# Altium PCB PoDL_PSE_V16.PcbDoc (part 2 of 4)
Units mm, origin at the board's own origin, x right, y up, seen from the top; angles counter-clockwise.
Board outline 155 x 86.5 mm, 4 copper layers (Top Layer, Signal Layer 2, Signal Layer 3, Bottom Layer), stack 1.586 mm thick; 431 components, 281 nets, 1286 pads, 864 vias.
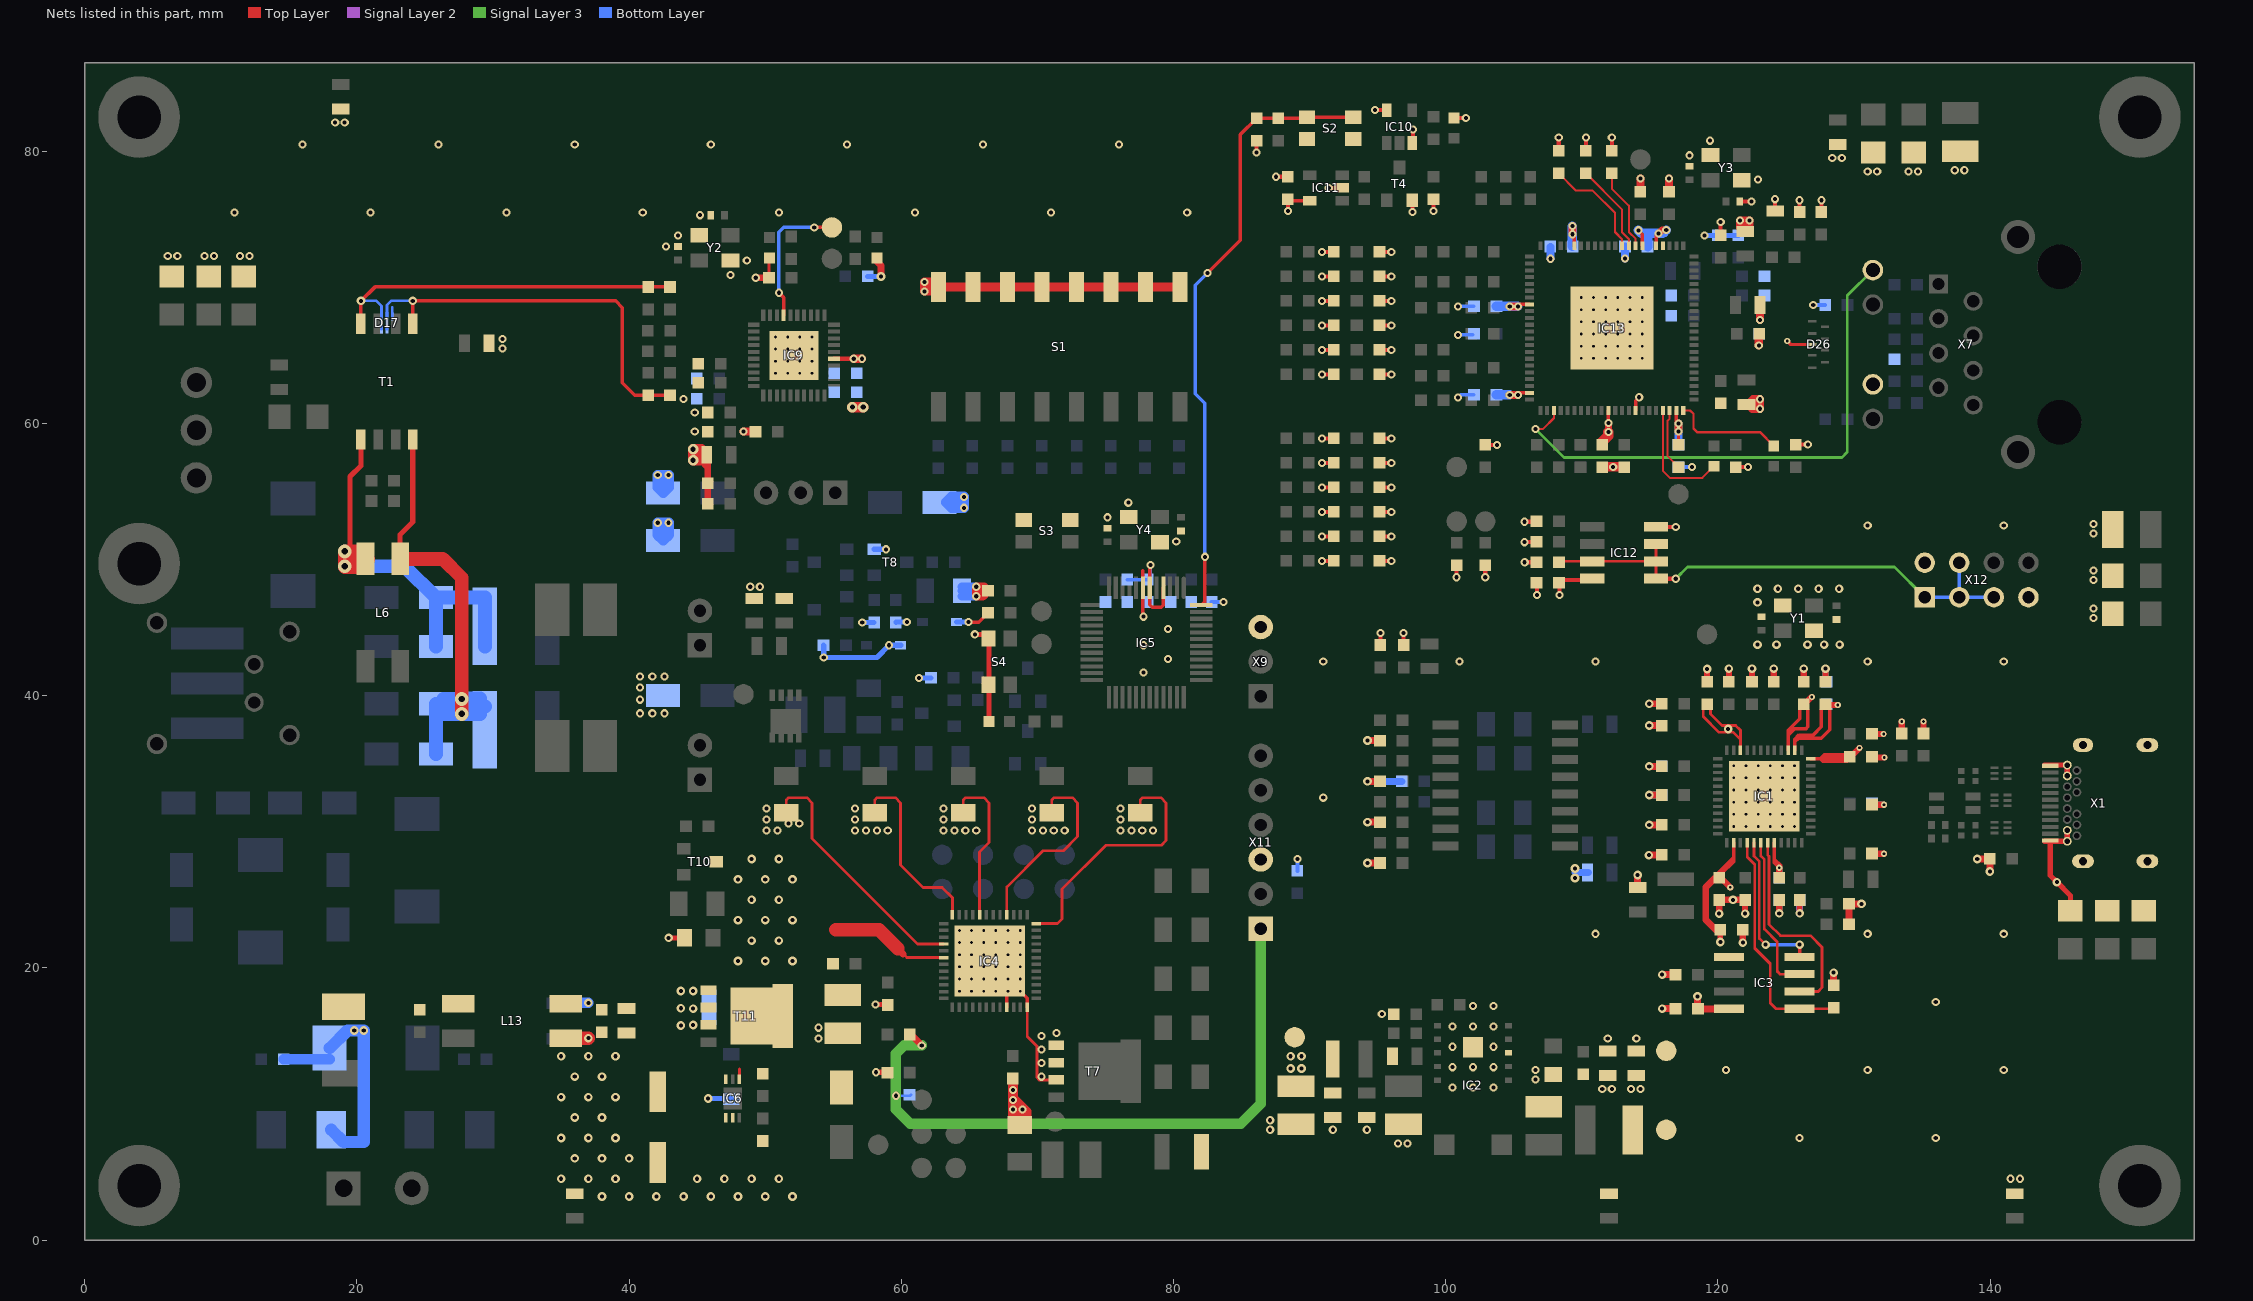
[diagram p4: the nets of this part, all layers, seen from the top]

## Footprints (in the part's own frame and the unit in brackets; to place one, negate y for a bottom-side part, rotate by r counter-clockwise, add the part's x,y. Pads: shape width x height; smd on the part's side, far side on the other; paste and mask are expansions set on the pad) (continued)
"QFN-88 12X12MM" [mm]
  rect 0.65x0.3 smd: 1(-6.05,5.25) 2(-6.05,4.75) 3(-6.05,4.25) 4(-6.05,3.75) 5(-6.05,3.25) 6(-6.05,2.75) 7(-6.05,2.25) 8(-6.05,1.75) 9(-6.05,1.25) 10(-6.05,0.75) 11(-6.05,0.25) 12(-6.05,-0.25) 13(-6.05,-0.75) 14(-6.05,-1.25) 15(-6.05,-1.75) 16(-6.05,-2.25) 17(-6.05,-2.75) 18(-6.05,-3.25) 19(-6.05,-3.75) 20(-6.05,-4.25) 21(-6.05,-4.75) 22(-6.05,-5.25) 45(6.05,-5.25) 46(6.05,-4.75) 47(6.05,-4.25) 48(6.05,-3.75) 49(6.05,-3.25) 50(6.05,-2.75) 51(6.05,-2.25) 52(6.05,-1.75) 53(6.05,-1.25) 54(6.05,-0.75) 55(6.05,-0.25) 56(6.05,0.25) 57(6.05,0.75) 58(6.05,1.25) 59(6.05,1.75) 60(6.05,2.25) 61(6.05,2.75) 62(6.05,3.25) 63(6.05,3.75) 64(6.05,4.25) 65(6.05,4.75) 66(6.05,5.25)
  rect 0.3x0.65 smd: 23(-5.25,-6.05) 24(-4.75,-6.05) 25(-4.25,-6.05) 26(-3.75,-6.05) 27(-3.25,-6.05) 28(-2.75,-6.05) 29(-2.25,-6.05) 30(-1.75,-6.05) 31(-1.25,-6.05) 32(-0.75,-6.05) 33(-0.25,-6.05) 34(0.25,-6.05) 35(0.75,-6.05) 36(1.25,-6.05) 37(1.75,-6.05) 38(2.25,-6.05) 39(2.75,-6.05) 40(3.25,-6.05) 41(3.75,-6.05) 42(4.25,-6.05) 43(4.75,-6.05) 44(5.25,-6.05) 67(5.25,6.05) 68(4.75,6.05) 69(4.25,6.05) 70(3.75,6.05) 71(3.25,6.05) 72(2.75,6.05) 73(2.25,6.05) 74(1.75,6.05) 75(1.25,6.05) 76(0.75,6.05) 77(0.25,6.05) 78(-0.25,6.05) 79(-0.75,6.05) 80(-1.25,6.05) 81(-1.75,6.05) 82(-2.25,6.05) 83(-2.75,6.05) 84(-3.25,6.05) 85(-3.75,6.05) 86(-4.25,6.05) 87(-4.75,6.05) 88(-5.25,6.05)
  rect 6.1x6.1 smd: 89(0,0)
  silkscreen extent -6.5,5.88 -6.25,6.13, body extent -6.05,-6.05 6.05,6.05, height 1
"QFP-48 7x7MM" [mm] "TQFP, 48-Leads, Body 9.2x9.2mm (max), Pitch 0.50mm, IPC Medium Density"
  oval 1.65x0.3 smd: 1(-4.025,2.75)
  rect 1.65x0.3 smd: 2(-4.025,2.25) 3(-4.025,1.75) 4(-4.025,1.25) 5(-4.025,0.75) 6(-4.025,0.25) 7(-4.025,-0.25) 8(-4.025,-0.75) 9(-4.025,-1.25) 10(-4.025,-1.75) 11(-4.025,-2.25) 12(-4.025,-2.75) 25(4.025,-2.75) 26(4.025,-2.25) 27(4.025,-1.75) 28(4.025,-1.25) 29(4.025,-0.75) 30(4.025,-0.25) 31(4.025,0.25) 32(4.025,0.75) 33(4.025,1.25) 34(4.025,1.75) 35(4.025,2.25) 36(4.025,2.75)
  rect 0.3x1.65 smd: 13(-2.75,-4.025) 14(-2.25,-4.025) 15(-1.75,-4.025) 16(-1.25,-4.025) 17(-0.75,-4.025) 18(-0.25,-4.025) 19(0.25,-4.025) 20(0.75,-4.025) 21(1.25,-4.025) 22(1.75,-4.025) 23(2.25,-4.025) 24(2.75,-4.025) 37(2.75,4.025) 38(2.25,4.025) 39(1.75,4.025) 40(1.25,4.025) 41(0.75,4.025) 42(0.25,4.025) 43(-0.25,4.025) 44(-0.75,4.025) 45(-1.25,4.025) 46(-1.75,4.025) 47(-2.25,4.025) 48(-2.75,4.025)
  silkscreen extent -4.2,-2.8 2.8,3.58, body extent -4.5,-4.5 4.5,4.5, height 1.45
RJ45_74990112116A [mm] "Ethernet Connectors WR-MJ Feml Shld Hztl 8P8C Tab Up LED&EMI"
  round 2.5 hole 1.6: B1(-7.9,3.05) B2(7.9,3.05)
  round 3.2 hole 3.25 unplated: H1(-5.715,0)
  round 3.25 hole 3.25 unplated: H2(5.715,0)
  rect 1.4x1.4 hole 0.9: P1(4.445,8.89)
  round 1.4 hole 0.9: P2(3.175,6.35) P3(1.905,8.89) P4(0.635,6.35) P5(-0.635,8.89) P6(-1.905,6.35) P7(-3.175,8.89) P8(-4.445,6.35)
  round 1.52 hole 1.02: P9(5.465,13.72) P10(2.925,13.72) P11(-2.925,13.72) P12(-5.465,13.72)
  silkscreen extent -9.99,-10.8 9.99,14.5, body extent -10.27,-10.8 10.27,14.5, height 15.78
SET [mm]
  rect 1.96x3.15 smd: 1(-2.45,0) 2(2.45,0)
  body extent -3.05,-1.4 3.05,1.29, height 2.68
SMA/DO-214AC [mm]
  rect 2.5x1.7 smd: 1(-2,0) 2(2,0)
  silkscreen extent -2.8,-1.5 2.8,1.5, body extent -2.65,-1.3 2.55,1.3, height 2.4
SMB/DO-214AA [mm]
  rect 2.159x2.743 smd: 1(-2.21,0) 2(2.21,0)
  silkscreen extent -2.16,-1.91 2.16,1.91, body extent -2.7,-1.74 2.7,1.86, height 2.3
SMC/DO-214AB [mm]
  rect 2.5x3.3 smd: 1(-3.4,0) 2(3.4,0)
  silkscreen extent -4.1,-3.15 4.1,3.15, body extent -3.97,-2.95 3.97,2.95, height 2.3
"SMT 6.3mmx5.5mm - WE" [mm]
  rect 1.2x3 smd: 1(0,2.6) 2(0,-2.6)
  silkscreen extent -3.4,-3.4 3.4,3.4, body extent -3.3,-3.65 3.3,3.65, height 5.5
SO-8 [mm]
  rect 0.72x1.78 smd: 1(-1.905,-2.34) 2(-0.635,-2.34) 3(0.635,-2.34) 4(1.905,-2.34) 5(1.905,2.34) 6(0.635,2.34) 7(-0.635,2.34) 8(-1.905,2.34)
  silkscreen extent -2.73,-2.22 2.5,1.4, body extent -2.5,-3.17 2.5,3.17, height 1.88
SO-8N [mm]
  rect 0.6x2.2 smd: 1(-1.905,-2.6) 2(-0.635,-2.6) 3(0.635,-2.6) 4(1.905,-2.6) 5(1.905,2.6) 6(0.635,2.6) 7(-0.635,2.6) 8(-1.905,2.6)
  silkscreen extent -2.87,-2.46 2.5,1.1, body extent -2.5,-3.17 2.5,3.17, height 1.88
SOD-123 [mm] "On Semi recommended land pattern"
  rect 0.915x1.22 smd: 1(-1.637,0) 2(1.637,0)
  silkscreen extent -2.74,-1.17 2.03,1.17, body extent -1.93,-0.9 1.93,0.9, height 1.35
SOD-323 [mm]
  rect 0.8x0.6 smd: 1(-1.25,0) 2(1.25,0)
  silkscreen extent -0.8,-0.7 0.8,0.7, body extent -1.3,-0.67 1.3,0.68, height 1.1
SOT-23 [mm]
  rect 0.85x1 smd: 1(-0.95,-1.2) 2(0.95,-1.2) 3(0,1.2)
  silkscreen extent -1.43,-0.3 1.43,1.2, body extent -1.46,-1.17 1.46,1.17, height 1
SOT-23-5 [mm] "TSOP-5, Case483-2"
  rect 0.7x1 smd: 1(-0.95,-1.2) 2(0,-1.2) 3(0.95,-1.2) 4(0.95,1.2) 5(-0.95,1.2)
  silkscreen extent -1.77,-1.57 1.53,0.88, body extent -1.46,-1.17 1.46,1.17, height 1
"TESTPOINT 1.5mm"#1 [mm]
  round 1.5 smd paste-1.5: 1(0,0)
"TESTPOINT 1.5mm"#2 [mm]
  round 1.5 smd paste+0: 1(0,0)
WE-5027-02P [mm] "Connector; Header; 2 Position;Pitch 5 mm."
  rect 2.5x2.5 hole 1.3: 1(-2.5,0)
  round 2.5 hole 1.3: 2(2.5,0)
  silkscreen extent -5.5,-3.3 5,4.2, body extent -5.5,-3.3 5,4.2, height 10.05
WE-TVS_824014885 [mm] "ESD Suppressors / TVS Diodes"
  rect 0.2x0.6 smd paste+0: 1(-1.7,-0.475) 2(-0.8,-0.475) 3(0,-0.475) 4(0.8,-0.475) 5(1.7,-0.475) 6(1.3,0.475) 7(0.4,0.475) 8(-0.4,0.475) 9(-1.3,0.475)
  silkscreen extent -1.9,-0.53 1.9,0.53, body extent -1.9,-0.5 1.9,0.5, height 0.5
WEEE_275x400 [mm]
  silkscreen extent -0.48,0 6.32,10.01
Wurth_994x400 [mm]
  silkscreen extent 0,-0.03 24.87,9.35

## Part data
C1: "CAP, CERM, 1nF, 50V, +/-10%, X7R, 0603", Dielectric=X7R, Manufacturer=Wurth, Supplier Part Number 1=710-885012206083, Tolerance_%=10%
C2: "CAP, CERM, 1uF, 50V, +/-10%, X7R, 0805", Dielectric=X7R, Manufacturer=Wurth, Supplier Part Number 1=710-885012207103, Tolerance_%=10
C3 C4 C5 C6 C10 C11 C12 C13 C14 C16 C21 C22 C23 C24 C40 C44 C46 C47 C48 C49 C50 C51 C57 C59 C62 C63 C66 C67 C68 C69 C70 C71 C72 C75 C76 C77 C78 C79 C80 C81 C84 C96 C118: "CAP, CERM, 100nF, 25V, +/-10%, X7R, 0603", Dielectric=X7R, Manufacturer=Wurth, Supplier Part Number 1=710-885012206071, Tolerance_%=10
C7 C8: "CAP, CERM, 100nF, 25V, +/-20%, X5R, 0402", Dielectric=X5R, Manufacturer=Wurth, Supplier Part Number 1=710-885012105018, Tolerance_%=20
C9 C18 C20 C29 C52 C60: "CAP, CERM, 1uF, 16V, +/-10%, X7R, 0603", Dielectric=X7R, Manufacturer=Wurth, Supplier Part Number 1=710-885012206052, Tolerance_%=10%
C15: "CAP, CERM, 22uF, 6.3V, +/-20%, X5R, 0805", Dielectric=X5R, Manufacturer=Wurth, Supplier Part Number 1=710-885012107005, Tolerance_%=20
C17: "CAP, CERM, 10uF, 6.3V, +/-20%, X5R, 0603", Dielectric=X5R, Manufacturer=Wurth, Supplier Part Number 1=710-885012106006, Tolerance_%=10
C19 C41 C116 C127: "CAP, CERM, 10nF, 100V, +/-10%, X7R, 1206", Dielectric=X7R, Manufacturer=Wurth, Supplier Part Number 1=710-885012208112, Tolerance_%=10
C25 C120: "CAP, CERM, 10uF, 50V, +/-10%, X7R, 1210", Dielectric=X7R, Manufacturer=Wurth, Supplier Part Number 1=710-885012209073, Tolerance_%=10%
C26 C34 C37 C105: "CAP, CERM, 100nF, 50V, +/-10%, X7R, 0805", Dielectric=X7R, Manufacturer=Wurth, Supplier Part Number 1=710-885012207098, Tolerance_%=10
C27 C28: "CAP, CERM, 10uF, 10V, +/-10%, X7R, 0805", Dielectric=X7R, Manufacturer=Wurth, Supplier Part Number 1=710-885012207026, Tolerance_%=10
C30 C31 C53 C54 C55 C56 C82 C83: "CAP, CERM, 15pF, 50V, +/-5%, C0G, 0402", Dielectric=C0G, Manufacturer=Wurth, Supplier Part Number 1=732-7470-1-ND, Tolerance_%=5
C32: "CAP, CERM, 470nF, 10V, +/-10%, X7R, 0603", Dielectric=X7R, Manufacturer=Wurth, Supplier Part Number 1=710-885012206024, Tolerance_%=10
C33 C119: "CAP, CERM, 100nF, 100V, +/-10%, X7R, 0603", Dielectric=X7R, Manufacturer=Wurth, Supplier Part Number 1=710-885012206120, Tolerance_%=10
C35 C38: "CAP, CERM, 2.2uF, 100V, +/-10%, X7R, 1210", Dielectric=X7R, Manufacturer=Wurth, Supplier Part Number 1=710-885382209002, Tolerance_%=10%
C36 C39: "CAP, CERM, 2.2nF, 50V, +/-10%, X7R, 0603", Dielectric=X7R, Manufacturer=Wurth, Supplier Part Number 1=710-885012206085, Tolerance_%=10%
C42: "CAP, CERM, 10nF, 1kV, +/-10%, X7R, 1206", Dielectric=X7R, Manufacturer=Wurth, Supplier Part Number 1=710-885342208021, Tolerance_%=10
C43: "CAP, CERM, 4.7uF, 10V, +/-20%, X5R, 0603", Dielectric=X5R, Manufacturer=Wurth, Supplier Part Number 1=710-885012106012, Tolerance_%=20%
C45 C58 C61 C64: "CAP, CERM, 10nF, 16V, +/-10%, X7R, 0603", Dielectric=X7R, Manufacturer=Wurth, Supplier Part Number 1=710-885012206040, Tolerance_%=10
C65: "CAP, CERM, 680nF, 16V, +/-10%, X7R, 0603", Dielectric=X7R, Manufacturer=Wurth, Supplier Part Number 1=710-885012206051, Tolerance_%=10
C73: "CAP, CERM, 1uF, 10V, +/-10%, X7R, 0603", Dielectric=X7R, Manufacturer=Wurth, Supplier Part Number 1=710-885012206026, Tolerance_%=10%
C74: "CAP, CERM, 470pF, 50V, +/-10%, X7R, 0603", Dielectric=X7R, Manufacturer=Wurth, Supplier Part Number 1=710-885012206081, Tolerance_%=10
C85 C86 C87 C88 C99 C100 C101 C102: "CAP, CERM, 10pF, 50V, +/-5%, C0G, 0603", Dielectric=C0G, Manufacturer=Wurth, Supplier Part Number 1=710-885012006051, Tolerance_%=5
C89 C98: "CAP, CERM, 22nF, 50V, +/-10%, X7R, 0603", Dielectric=X7R, Manufacturer=Wurth, Supplier Part Number 1=710-885012206091, Tolerance_%=10%
C90 C93: library part TBE_CAP_1210, "CAP, CERM, TBE, 1210"
C91 C92 C94 C95: library part TBE_CAP_1206, "CAP, CERM, TBE, 1206"
C97 C104 C106 C107 C108 C109: "CAP, CERM, 10nF, 100V, +/-10%, X7R, 0603", Dielectric=X7R, Manufacturer=Wurth, Supplier Part Number 1=710-885012206114, Tolerance_%=10%
C103: "CAP, CERM, 1nF, 100V, +/-10%, X7R, 0805", Dielectric=X7R, Manufacturer=Wurth, Supplier Part Number 1=710-885012207116, Tolerance_%=10
C110 C111: "CAP, CERM, 10nF, 200V, +/-10%, X7R, 0805", Dielectric=X7R, Manufacturer=Wurth, Supplier Part Number 1=710-885342207005, Tolerance_%=10
C112 C113 C114 C115 C122: "CAP, CERM, 47nF, 50V, +/-10%, X7R, 0603", Dielectric=X7R, Manufacturer=Wurth, Supplier Part Number 1=710-885012206093, Tolerance_%=10%
C117: library part TBE_CAP_0603, "CAP, CERM, TBE, 0603"
C121: "CAP, ECAP, 22uF, 50V, +/-20%, 6.3mm x 5.5mm", Dielectric=-, Manufacturer=Wurth, Supplier Part Number 1=710-865080643008, Tolerance_%=20
C123 C124: "CAP, CERM, 4.7uF, 50V, +/-10%, X7R, 1210", Dielectric=X7R, Manufacturer=Wurth, Supplier Part Number 1=710-885012209048, Tolerance_%=10%
C125: "CAP, CERM, 1uF, 16V, +/-10%, X7R, 0805", Dielectric=X7R, Manufacturer=Wurth, Supplier Part Number 1=710-885012207051, Tolerance_%=10
C126: "CAP, CERM, 1nF, 50V, +/-5%, C0G, 0805", Dielectric=C0G, Manufacturer=Wurth, Supplier Part Number 1=710-885012007063, Tolerance_%=5
D1: "DIODE, TVS , 33V, 1.5kW, Bidirection, SMC", Manufacturer=Wurth, Power=1500W, Supplier Part Number 1=710-824541331, Temperature="-65°C ~ 150°C", Voltage=33V
D2 D3 D4 D17: "DIODE, TVS Super Speed , 3.3V, DFN1210-6L", Manufacturer=Wurth, Supplier Part Number 1=710-824012823, Temperature="-55°C ~ 85°C", Voltage=3.3V
D5 D20: "LED 570NM GREEN 0805 SMD", Manufacturer=Wurth, Supplier Part Number 1=710-150080VS75000
D6 D7 D8: "DIODE, TVS , 5V, 400W, Unidirection, SMA", Manufacturer=Wurth, Power=400W, Supplier Part Number 1=710-824500500, Temperature="-55°C ~ 150°C", Voltage=5V
D9 D10 D11 D12 D15 D16: "DIODE, Rectifiers, 100V, 1A, SMA", Manufacturer=Diodes, Supplier Part Number 1=621-S1B-F, Temperature="-65°C ~ 150°C", Voltage=100V
D13 D33 D36: "DIODE, TVS , 36V, 1.5kW, Bidirection, SMC", Manufacturer=Wurth, Power=1500W, Supplier Part Number 1=710-824541361, Temperature="-55°C ~ 150°C", Voltage=36V
D14 D18: "DIODE, Schottky, 30V, 0.1A, SOD-323", Manufacturer="Diodes Inc", Supplier Part Number 1=621-BAT54WS-F, Temperature="-65°C ~ 125°C", Voltage=30V
D19: "DIODE, Switching, 100V, 0.2A, SOT-23", Manufacturer=Onsemi, Supplier Part Number 1=863-MMBD914LT1G, Temperature="-55°C ~ 150°C", Voltage=100V
D21: "LED 470NM BLUE 0603 SMD", Manufacturer=Wurth, Supplier Part Number 1=710-150060BS55040
D22 D29: "DIODE, TVS , 24V, 600W, Unidirection, SMB", Manufacturer=Wurth, Power=600W, Supplier Part Number 1=710-824520241, Temperature="-65°C ~ 150°C", Voltage=24V
D23: "LED 587NM YELLOW 0603 SMD", Manufacturer="Lite-On Inc.", Supplier Part Number 1=859-LTST-C190KSKT
D24 D27 D28: "LED 572NM GREEN 0603 SMD", Manufacturer=Wurth, Supplier Part Number 1=710-150060VS75020
D25: "LED 645NM RED 0603 SMD", Manufacturer=Wurth, Supplier Part Number 1=710-150060SS75020
D26: "DIODE, TVS Super Speed , 5V, 8CH, 3.8x1.0mm", Manufacturer=Wurth, Supplier Part Number 1=710-824014885, Temperature="-55°C ~ 85°C", Voltage=5V/0.5pF
D30: "Gas Discharge Tubes, 150V, 1pF, 5x7.5mm, SMD", Manufacturer=Bourns, Supplier Part Number 1=652-2038-15-SM-RPLF
D31 D32 D34 D35: "DIODE, Rectifiers, 200V, 1A, SMA", Manufacturer=Diodes, Supplier Part Number 1=621-S1D-F, Temperature="-65°C ~ 150°C", Voltage=200V
F1: "FUSE, SMT, 2.0A, 125V, Slow Blow, 6.1x 2.69mm", Manufacturer=Littelfuse, Supplier Part Number 1=576-0454002.MR
FB1 FB2 FB3 FB4 FB5 FB6 FB10: "Ferrite Bead 300R @ 100MHz / 0805 / 3.0A", Manufacturer=Wurth, Supplier Part Number 1=710-742792031
FB8: "Ferrite Bead 600R @ 100MHz / 0805 / 2.0A", Manufacturer=Wurth, Supplier Part Number 1=710-742792040
FB9: "Ferrite Bead 120R @ 100MHz / 0603 / 2.0A", Manufacturer=Wurth, Supplier Part Number 1=710-742792625
H1 H2 H3 H4 H5: Manufacturer=xxxx, Temperature="-55 to 150 °C"
HGATE0 HGATE1 HGATE2 HGATE3 HGATE4 LGATE LSNS OUTP1 OUTP2 OUTP3 OUTP4 SCCPI SCCPO SW0 SW1 SW2 SW3 SW4 TP1 TP2 TP3 TP4 TP5 TP6 TP7 TP8 TP9 TP10 TP11: library part "TP / 1.5mm", "Test Point, SMT, Miniature"
IC1: "IC USB3.1 to 1G Ethernet Bridge, 3.3V, QFN-48", Manufacturer=Microchip, Supplier Part Number 1=579-LAN7800/Y9X
IC2: "IC REG BUCK, ADJ, 3A, LGA-16EP", Manufacturer=Wurth, Supplier Part Number 1=710-171033801
IC3: "IC EEPROM, SPI, 4kb, 16MHz, 1.8-5.5V, SO-8", Manufacturer=Microchip, Supplier Part Number 1=579-93AA66C-I/SN
IC4: "IC SPoE PSE, 5-Ports, 10Base-T1L, 6-60V, QFN-48", Manufacturer="Analog Devices"
IC5: "IC MCU, STM32G030C8T6, 32bit, 64kB, 64MHz,  LQFP-48", Manufacturer=ST, Supplier Part Number 1=511-STM32G030C8T6
IC6: "IC PMIC, Ideal Diode, 4-80V, DFN-6", Manufacturer="Analog Devices", Supplier Part Number 1=584-C4359CDCBTRMPBF
IC9: "IC Ethernet 10BASE-T1L PHY, 3.3V, LFCSP-40", Manufacturer=Microchip, Supplier Part Number 1=505-ADIN1100CCPZ-R7CT-ND
IC10: library part 74LVC1G14GV,125_2, "IC SCHMITT INVERTER, 1.65-5.5V, 1CH, SOT-753", Manufacturer=Nexperia, Supplier Part Number 1=771-74LVC1G14GV
IC11: "IC Supervisory, 0.75-3.3V, SOT-23-5", Manufacturer=TI, Supplier Part Number 1=595-TPS3125L30DBVR, Threshold Voltage=2.64V
IC12: "IC EEPROM, I2C, 512kb, 1MHz, 1.7-5.5V, SO-8", Manufacturer=Microchip, Supplier Part Number 1=579-24FC512-I/SN
IC13: "IC ETHERNET SWITCH 3PORT, VQFN-88", Manufacturer=Microchip, Supplier Part Number 1=LAN9355I/ML-ND
L1: "Coupled Inductor 2x470uH / 12.5x12.5mm /0.7A", Manufacturer=Wurth, PartNumber=744870471
L2 L3: "Common Mode Chokes 60R @ 100MHz / 1x1.2mm / 600mA", Manufacturer=Wurth, Supplier Part Number 1=710-7442335600
L4: "Inductor 3.3uH / 3015 / 1.5A", Inductance=3.3uH, Manufacturer=Wurth, Supplier Part Number 1=710-74404032033
L5: "Common Mode Chokes 90R @ 100MHz / 1206 / 370mA", Manufacturer=Wurth, Supplier Part Number 1=710-744232090
L6: "Common Mode Chokes 2x250uH / 9.2x6mm / 1200mA", Manufacturer=Wurth, Supplier Part Number 1=710-744224
L8 L10: "Inductor 22uH / 6045 / 2.1A", Inductance=22uH, Manufacturer=Wurth, Supplier Part Number 1=710-74404064220
L11: "Inductor 22uH / 3015 / 0.6A", Inductance=22uH, Manufacturer=Wurth, Supplier Part Number 1=710-74404032220
L12: "Inductor 4.7uH / 4018 / 1.7A", Inductance=4.7uH, Manufacturer=Wurth, Supplier Part Number 1=710-74404042047
L13: "Common Mode Chokes 2x1000uH / 9.2x6mm / 800mA", Manufacturer=Wurth, Supplier Part Number 1=710-744222
R2 R3 R16 R27 R65 R68: "RES, 5.1kohm, 1%, 0.1W, 0603", Manufacturer=Yageo, Power_W=0.1, Supplier Part Number 1=603-RC0603FR-075K1L, Tolerance_%=1%
R4 R40 R90 R91 R92 R93: "RES, 330 ohm, 1%, 0.1W, 0603", Manufacturer=Wurth, Power_W=0.1, Supplier Part Number 1=710-560112116020, Tolerance_%=1%
R5 R6 R12 R17 R18 R30 R61 R63 R66 R67 R73 R82 R84 R88 R89 R100 R101 R102 R103 R104 R105 R138 R139 R140 R141 R142 R143 R151 R152: "RES, 10kohm, 1%, 0.1W, 0603", Manufacturer=Wurth, Power_W=0.1, Supplier Part Number 1=710-560112116005, Tolerance_%=1%
R7 R74 R85 R86: "RES, 2kohm, 1%, 0.1W, 0603", Manufacturer=Wurth, Power_W=0.1, Supplier Part Number 1=710-560112116091, Tolerance_%=1%
R8: "RES, 10kohm, 1%, 0.1W, 0603", Manufacturer=Yageo, Power_W=0.1, Supplier Part Number 1=603-RC0603FR-0710KL, Tolerance_%=1%
R9: "RES, 24.3kohm, 1%, 0.1W, 0603", Manufacturer=Yageo, Power_W=0.1, Supplier Part Number 1=603-RC0603FR-0724K3L, Tolerance_%=1%
R10: "RES, 402kohm, 1%, 0.1W, 0603", Manufacturer=Yageo, Power_W=0.1, Supplier Part Number 1=603-RC0603FR-07402KL, Tolerance_%=1%
R11: "RES, 12kohm, 1%, 0.1W, 0603", Manufacturer=Wurth, Power_W=0.1, Supplier Part Number 1=710-560112116040, Tolerance_%=1%
R13: "RES, 49.9 ohm, 1%, 0.25W, 1206", Manufacturer=Yageo, Power_W=0.25, Supplier Part Number 1=603-RC1206FR-0749R9L, Tolerance_%=-
R14: "RES, 20 ohm, 1%, 0.25W, 1206", Manufacturer=Wurth, Power_W=0.25, Supplier Part Number 1=710-560112132008, Tolerance_%=-
R15 R32: "RES, 5.1 ohm, 1%, 0.25W, 1206", Manufacturer=Yageo, Power_W=0.25, Supplier Part Number 1=603-RC1206FR-075R1L, Tolerance_%=-
R19 R20 R21 R22 R23: "RES, 0 ohm, -%, 0.125W, 0805", Manufacturer=Yageo, Power_W=0.125, Supplier Part Number 1=311-0.0ARCT-ND, Tolerance_%=-%
R24: "RES, 49.9kohm, 1%, 0.5W, 1210", Manufacturer=YAGEO, Power_W=0.5W, Supplier Part Number 1=603-RC1210FR-0749K9L, Tolerance_%=1%
R25: "RES, 1 ohm, 1%, 0.25W, 1206", Manufacturer=Wurth, Power_W=0.25W, Supplier Part Number 1=710-560112132002, Tolerance_%=1%
R26 R33 R35 R37: "RES, 100kohm, 1%, 0.1W, 0603", Manufacturer=Wurth, Power_W=0.1, Supplier Part Number 1=710-560112116004, Tolerance_%=1%
R28: "RES, 5.6kohm, 1%, 0.1W, 0603", Manufacturer=Wurth, Power_W=0.1, Supplier Part Number 1=710-560112116017, Tolerance_%=1%
R31: "RES, 49.9kohm, 1%, 0.1W, 0603", Manufacturer=Wurth, Power_W=0.1, Supplier Part Number 1=710-560112116112, Tolerance_%=1%
R34: "RES, 137kohm, 1%, 0.1W, 0603", Manufacturer=Yageo, Power_W=0.1, Supplier Part Number 1=603-RC0603FR-07137KL, Tolerance_%=1%
R36: "RES, 100kohm, 1%, 0.25W, 1206", Manufacturer=Wurth, Power_W=0.25, Supplier Part Number 1=710-560112132034, Tolerance_%=-
R38: "RES, 100kohm, 1%, 0.1W, 0603", Manufacturer=Yageo, Power_W=0.1, Supplier Part Number 1=603-RC0603FR-07100KL, Tolerance_%=1%
R39 R52 R53 R54 R55 R56 R57 R58 R59 R60 R62 R72 R87: "RES, 4.7kohm, 1%, 0.1W, 0603", Manufacturer=Wurth, Power_W=0.1, Supplier Part Number 1=710-560112116006, Tolerance_%=1%
R41: library part TBE_RES_1210, "RES, TBE, 1%, 0.5W, 1210", Power_W=0.5W, Tolerance_%=1%
R42: "RES, 100 ohm, 1%, 0.125W, 0805", Manufacturer=Wurth, Power_W=0.125, Supplier Part Number 1=710-560112120020, Tolerance_%=1%
R43 R76: "RES, 1kohm, 1%, 0.1W, 0603", Manufacturer=Wurth, Power_W=0.1, Supplier Part Number 1=710-560112116014, Tolerance_%=1%
R64 R69 R77 R78 R79 R80 R154 R155 R156 R157: "RES, 49.9 ohm, 1%, 0.1W, 0603", Manufacturer=Wurth, Power_W=0.1, Supplier Part Number 1=710-560112116133, Tolerance_%=1%
R70 R71 R150: "RES, 1.5kohm, 1%, 0.1W, 0603", Manufacturer=Wurth, Power_W=0.1, Supplier Part Number 1=710-560112116038, Tolerance_%=1%
R75: "RES, 100 ohm, 1%, 0.1W, 0603", Manufacturer=Wurth, Power_W=0.1, Supplier Part Number 1=710-560112116009, Tolerance_%=1%
R81 R94 R95 R96 R97 R98 R99 R106 R107 R108 R109 R110 R111 R132 R133 R134 R135 R136 R137 R144 R145 R146 R147 R148 R149 R153 R162: "RES, 0 ohm, 1%, 0.1W, 0603", Manufacturer=Yageo, Power_W=0.1, Supplier Part Number 1=603-RC0603FR-070RL, Tolerance_%=1%
R83: "RES, 12.1kohm, 1%, 0.1W, 0603", Manufacturer=Yageo, Power_W=0.1, Supplier Part Number 1=603-RC0603FR-0712K1L, Tolerance_%=1%
R112 R113 R114 R115 R116 R117 R118 R119 R120 R121 R122 R123 R124 R125 R126 R127 R128 R129 R130 R131: "RES, 33 ohm, 1%, 0.1W, 0603", Manufacturer=Wurth, Power_W=0.1, Supplier Part Number 1=710-560112116034, Tolerance_%=1%
R158 R159: "RES, 75 ohm, 1%, 0.125W, 0805", Manufacturer=Yageo, Power_W=0.125, Supplier Part Number 1=603-RC0805FR-0775RL, Tolerance_%=1%
R160 R161 R198 R199 RSH1 RSH2 RSH3 RSH4 RSL1 RSL2 RSL3 RSL4: "RES, 0 ohm, -%, 0.25W, 1206", Manufacturer=Vishay, Power_W=0.25, Supplier Part Number 1=541-0.0ECT-ND, Tolerance_%=-
RSH0: "RES, 0.24 ohm, 1%, 0.25W, 1206", Manufacturer=YAGEO, Power_W=1, Supplier Part Number 1=603-RL1206FR-070R24L, Tolerance_%=-
RSL0: "RES, 0.062 ohm, 1%, 0.25W, 1206", Manufacturer=YAGEO, Power_W=1, Supplier Part Number 1=603-RL1206FR070R062L, Tolerance_%=-
S1: "DIP SWITCH, SPST, 0.025A, 24V", Manufacturer=Wurth, Supplier Part Number 1=710-418121270808
S2 S3 S4: "SWITCH TACTILE, SPST-NO, 350gf, 0.05A, 12V", Manufacturer=Wurth, Supplier Part Number 1=710-434153017835
T1: "Trans, PoDL, 2.2mH, SMT", Manufacturer=Wurth
T2: "MOSFET, N-CH, 100V, 18A, LFPAK33", Manufacturer=Nexperia, Supplier Part Number 1=771-PSMN075-100MSEX
T3 T5 T10: "MOSFET, N-CH, 100V, 0.17A, SOT-23", Manufacturer=Onsemi, Supplier Part Number 1=863-BSS123LT1G
T4: "MOSFET, N-CH, 50V, 0.2A, SOT-23", Manufacturer=Onsemi, Supplier Part Number 1=863-BSS138LT1G
T6: "Transistor, NPN, 80V, 0.5A, SOT-23", Manufacturer="ON Semi", Supplier Part Number 1=863-MMBTA06LT1G
T7: "MOSFET, N-CH, 100V, 43A, LFPAK56", Manufacturer=Nexperia, Supplier Part Number 1=771-PSMN020-100YS115
T8 T9: "Transistor, NPN, 40V, 0.2A, SOT-23", Manufacturer="ON Semi", Supplier Part Number 1=863-MMBT3904LT1G
T11: "MOSFET, N-CH, 100V, 24.8A, LFPAK56", Manufacturer=Nexperia, Supplier Part Number 1=771-BUK7Y53-100B,115
VAR1 VAR2: "Varistor, 85Vdc, 60Vac, 160pF, 1206", Manufacturer=Wurth, Supplier Part Number 1=710-82551600
X1: "CON, USB, Type C, Female, 24P, Hor, SMT", Manufacturer=Wurth, Supplier Part Number 1=710-632723300011
X2: "CON, SPE, 2P, Shield, 4A, R/A, INS", Manufacturer=HARTING, Supplier Part Number 1=617-09452812810
X3: "CON, Terminal Block, Plug-in, 3P, P3.5mm, 10A, R/A, INS", Manufacturer=Wurth, Supplier Part Number 1=710-691322110003
X4: "CON, Terminal Block, Screw, 2P, P5.0mm, 15A, INS", Manufacturer=Wurth, Supplier Part Number 1=710-691502710002
X5 X10: "CON, Header, Male, 2P, P2.54mm, Straight, INS", Manufacturer=Wurth, Supplier Part Number 1=710-61300211121
X6 X9: "CON, Header, Male, 3P, P2.54mm, Straight, INS", Manufacturer=Wurth, Supplier Part Number 1=710-61300311121
X7: "CON, Ethernet, Int Magnetics, 8P+LED, 1x1 Tab-UP, INS", Manufacturer=Wurth, Supplier Part Number 1=710-74990112116A
X8: "Trans, Ethernet, 10/100 Base-T, SMT", Manufacturer=Wurth, Supplier Part Number 1=710-7490100110A
X11: "CON, Header, Male, 6P, P2.54mm, Straight, INS", Manufacturer=Wurth, Supplier Part Number 1=710-61300611121
X12: "CON, Header, Male, 2x4P, P2.54mm, Straight, INS", Manufacturer=Wurth, Supplier Part Number 1=710-61300821121
Y1 Y2 Y3: "Crystal / 25MHz / 18pF / 30ppm", Load Capacitance=18pF, Manufacturer=Wurth, Package=3.2x2.5x0.8mm, Supplier Part Number 1=710-830055299
Y4: "Crystal / 8MHz / 12pF / 30ppm", Load Capacitance=12pF, Manufacturer=Wurth, Package=3.2x2.5x0.8mm, Supplier Part Number 1=710-830108313809
Z1: "DIODE, ZENER, 12V, 500MW, SOD-123", Manufacturer="Diodes Inc"

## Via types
v1: diameter 0.6, hole 0.3, Top Layer to Bottom Layer, tented both sides, 494 vias
v2: diameter 0.45, hole 0.2, Top Layer to Bottom Layer, tented both sides, 173 vias
v3: diameter 0.635, hole 0.3, Top Layer to Bottom Layer, tented both sides, 145 vias
v4: diameter 1.016, hole 0.508, Top Layer to Bottom Layer, 40 vias
v5: diameter 1.016, hole 0.457, Top Layer to Bottom Layer, tented both sides, 8 vias
v6: diameter 0.762, hole 0.381, Top Layer to Bottom Layer, tented both sides, 4 vias

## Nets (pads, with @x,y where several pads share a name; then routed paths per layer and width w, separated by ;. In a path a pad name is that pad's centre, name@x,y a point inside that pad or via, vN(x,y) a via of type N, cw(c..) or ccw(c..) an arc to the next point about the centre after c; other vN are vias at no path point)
+3V3: C16.1 C17.2 C18.1 C21.1 C22.1 C23.1 C24.1 C27.1 C28.1 C40.1 C43.1 C44.1 C50.1 C51.1 C61.1 C62.1 C66.2 C67.1 C68.1 C69.1 C70.1 C71.1 C72.1 C84.2 D14.2 D23.2 D24.2 FB1.1 FB2.1 FB4.1 FB6.1 FB9.2 IC1.14 IC1.20 IC1.36 IC1.38 IC1.39 IC1.46 IC3.8 IC5.4 IC5.6 IC9.35 IC10.5 IC11.5 IC12.8 IC13.5 IC13.7 IC13.17 IC13.30 IC13.43 IC13.55 IC13.65 L12.2 R3.1 R4.1 R5.1 R6.1 R8.2 R16.1 R31.1 R38.1 R39.1 R60.2 R61.2 R70.1 R71.1 R72.1 R73.2 R85.1 R86.1 R89.1 R90.2 R92.1 R93.1 R94.2 R95.2 R96.2 R97.2 R98.2 R99.2 R132.2 R133.2 R134.2 R135.2 R136.2 R137.2 R150.2 R152.1 S1.9 S1.10 S1.11 S1.12 S1.13 S1.14 S1.15 S1.16 TP10.1 X11.1 X12.2 | length 215.8
  Top Layer w0.2: C18.1@118.92,39.05 118.92,38.47 120.085,37.305 121.133,37.305 121.65,36.788 ; C18.1@119.45,38.98 119.45,38.655 120.3,37.805 121.3,37.805 121.65,37.455 121.65,36.788 ; IC1.46@121.65,36 121.65,36.788 ; C24.1@126,38.98 C24.1@126.3,39.28
  Top Layer w0.25: R61.2@50.274,70.7 50.274,72.125 D23.2@50.3,72.15 ; C16.1@119.893,26.848 121.15,28.105 ; C16.1@120.25,26.688 120.25,26.905 121.15,27.805 121.15,28.105 ; IC1.14@121.15,29.2 121.15,28.105 ; IC1.20@124.15,29.2 124.15,27.981 ; C21.1@124.4,26.84 124.4,27.457 124.15,27.707 124.15,27.981 ; C21.1@124.5,26.581 124.6,26.681 124.6,27.531 124.15,27.981 ; IC1.36@126.8,35.35 127.525,35.35 ; 127.805,35.65 C22.1@129.475,35.65 ; C22.1@129.425,35.58 127.755,35.58 127.525,35.35 ; C22.1@129.499,35.18 127.695,35.18 127.525,35.35 ; C22.1@129.499,35.28 C22.1@129.569,35.35 ; C22.1@129.669,35.35 C22.1@129.569,35.35 ; C22.1@129.7,35.48 C22.1@129.569,35.35 ; 127.525,35.35 C22.1@129.569,35.35
  Top Layer w0.254: v1(64.925,45.4) 65.674,45.4 R39.1@66.375,46.1 ; v1(78.3,49.6) 78.25,49.55 IC5.6@78.25,47.925 78.25,46.675 78.425,46.5 79.1,46.5 79.25,46.65 IC5.4@79.25,47.925 ; C66.2@88.4,76.475 88.525,76.35 IC11.5@90,76.35 ; v1@105.45,62.25 IC13.43@106.15,62.25 ; v1@105.473,68.75 IC13.30@106.15,68.75 ; IC13.17@109.45,73.05 v1@109.45,73.727 ; v1(111.95,60.039) IC13.55@111.95,60.95 ; v1(114.15,74.188) 114.45,73.888 IC13.7@114.45,73.05 ; IC13.5@115.45,73.05 115.45,73.774 v1(115.635,73.959) ; v1@116.95,59.6 IC13.65@116.95,60.95 ; R89.1@117.1,58.426 v1(117.1,59.4) ; FB6.1@121.75,61.4 FB6.1@122,61.4 ; IC1.39@125.15,36 125.15,37.105 ; IC1.38@125.65,36 125.65,36.605 ; C24.1@126,38.98 126,38.305 125.15,37.455 125.15,37.105 ; C24.1@126.3,39.28 126.6,38.98 126.6,37.705 126.445,37.55 125.595,37.55 125.15,37.105 ; 125.65,36.605 125.925,36.881 127.576,36.881 128.2,37.505 128.2,38.98 127.9,39.28 127.6,38.98 127.6,37.705 127,37.105 125.955,37.105 125.65,36.8 125.65,36.605
  Top Layer w0.3: v1(86.1,79.9) R73.2@86.1,80.775 ; v1(88.4,75.6) C66.2@88.4,76.475 ; v1(94.8,83.035) IC10.5@95.675,83.035 ; R136.2@95.125,49.9 v1(96,49.9) ; R137.2@95.125,51.7 v1(96,51.7) ; R135.2@95.125,53.5 v1(96,53.5) ; R134.2@95.125,55.3 v1(96,55.3) ; R133.2@95.125,57.1 v1(96,57.1) ; R132.2@95.125,58.9 v1(96,58.9) ; R98.2@95.125,63.6 v1(96,63.6) ; R99.2@95.125,65.4 v1(96,65.4) ; R97.2@95.125,67.2 v1(96,67.2) ; R96.2@95.125,69 v1(96,69) ; R95.2@95.125,70.8 v1(96,70.8) ; R94.2@95.125,72.6 v1(96,72.6) ; v1(99.1,75.6) R72.1@99.1,76.475 ; v1(102.9,48.7) R150.2@102.9,49.575 ; R152.1@102.9,58.426 v1(103.774,58.425) ; v1(105.775,51.275) R85.1@106.649,51.275 ; v1(105.775,52.775) R86.1@106.649,52.775 ; v1(108.351,47.4) C84.2@108.351,48.275 ; C84.2@108.43,48.5 IC12.8@110.8,48.5 ; R93.1@121.325,56.8 v1(122.2,56.8) ; R92.1@125.725,58.451 v1(126.6,58.451)
  Top Layer w0.305: IC9.35@55.05,64.75 v1(56.5,64.75)
  Top Layer w0.381: R3.1@60.625,15.1 R3.1@60.7,15.1
  Top Layer w0.4: v3(120.174,21.895) C17.2@120.174,22.8
  Top Layer w0.45: C16.1@120.323,26.497 v2(120.905,25.915) ; C24.1@126.318,39.323 v2(126.9,39.905) ; C23.1@127.9,39.28 127.926,39.305 v2(128.8,39.305) ; C22.1@129.825,35.58 v2(130.407,36.162) ; R6.1@133.5,37.226 v2(133.5,38.1)
  Top Layer w0.5: C17.2@119.905,22.751 119.1,23.555 119.1,25.907 119.754,26.561 C16.1@120.09,26.561
  Top Layer w0.508: FB1.1@45.3,57.3 45.3,57.275 45.774,56.8 ; FB1.1@45.7,57.7 45.774,57.625 45.774,56.8 ; R71.1@45.775,54.1 45.774,56.8 ; v3(49.3,70.7) R61.2@50.274,70.7 ; D24.2@58.2,72.15 58.2,71.9 58.5,71.6 v3(58.5,70.8) ; R3.1@60.7,15.1 v1(61.5,14.3) ; v1(111.95,59.361) v1(111.95,60.039) ; v1(115.635,73.959) 115.876,74.2 v1(116.2,74.2) ; v3(118.5,17.9) 118.5,17 118.526,16.975 120.78,16.975 IC3.8@120.8,16.995 ; R8.2@129.626,23.2 R5.1@129.626,24.7 v3(130.55,24.7)
  Top Layer w0.6: v1(56.5,64.75) v1(57.1,64.75) ; v1(104.7,62.1) v1(105.3,62.1) ; v1(104.7,68.6) v1(105.3,68.6) ; v1(109.3,73.9) v1(109.3,74.5) ; v1(117.1,59.4) v1(117.1,60) ; v1(123.1,67.597) FB2.1@123.1,68.7 ; 121.975,74.9 v1(122.325,74.9) 122.325,74.325 FB4.1@122,74 ; 121.975,74.9 v1(121.625,74.9) 121.625,74.375 FB4.1@122,74 ; 121.975,74.9 122,74.875 FB4.1@122,74 ; FB6.1@122.2,61.4 122.525,61.075 v1(123.1,61.075) 123.1,61.425 ; FB6.1@122.2,61.4 122.575,61.775 v1(123.1,61.775) 123.1,61.425 ; FB6.1@122.2,61.4 123.075,61.4 123.1,61.425
  Top Layer w0.635: S1.9@80.47,70.025 S1.10@77.93,70.025 S1.11@75.39,70.025 S1.12@72.87,70.025 S1.13@70.33,70.025 S1.14@67.79,70.025 S1.15@65.27,70.025 S1.16@62.73,70.025 ; 61.7,70.05 61.725,70.025 S1.16@62.73,70.025 ; 61.7,70.05 v1(61.7,69.7) 62.405,69.7 S1.16@62.73,70.025 ; 61.7,70.05 v1(61.7,70.4) 62.355,70.4 S1.16@62.73,70.025
  Top Layer w0.762: v6(56.4,61.2) v6(57.2,61.2) ; C71.1@111.5,58.646 111.95,59.096 v1(111.95,59.361) ; 44.7,57.7 FB1.1@45.7,57.7 ; 44.7,57.7 v6(44.7,57.3) 45.3,57.3 FB1.1@45.7,57.7 ; 44.7,57.7 v6(44.7,58.1) 45.3,58.1 FB1.1@45.7,57.7
  Signal Layer 3 w0.762: v1(61.5,14.3) 60.2,14.3 59.6,13.7 v1(59.6,10.6) 59.6,9.6 60.65,8.55 84.925,8.55 86.4,10.025 X11.1@86.4,22.88
  Bottom Layer w0.203: v1(59.6,10.6) 60.625,10.6 R38.1@60.7,10.675
  Bottom Layer w0.254: C44.1@76.6,48.526 C43.1@78.1,48.526 78.3,48.726 v1(78.3,49.6)
  Bottom Layer w0.3: FB9.2@82.8,46.875 v1(83.674,46.875) ; v1(127,68.7) R90.2@127.874,68.7
  Bottom Layer w0.381: R60.2@57.526,70.8 v3(58.5,70.8) ; R31.1@59.6,45.375 59.626,45.4 v1(60.4,45.4) ; v1(61.3,41.3) R16.1@62.174,41.3 ; D14.2@64.05,45.4 v1(64.925,45.4)
  Bottom Layer w0.45: C51.1@128.026,39.305 v2(128.8,39.305)
  Bottom Layer w0.508: C50.1@124.5,26.581 C50.1@124.5,26.626 v2(124.5,27.355)
  Bottom Layer w0.6: v1(104.7,62.1) v1(105.3,62.1) ; C68.1@109.3,73.026 C68.1@109.326,73 ; C72.1@117.1,58.526 v1(117.1,59.4) v1(117.1,60)
  Bottom Layer w0.7: C70.1@103.725,62.1 v1(104.7,62.1) ; C69.1@103.725,68.6 v1(104.7,68.6) v1(105.3,68.6) ; C68.1@109.3,73.026 v1(109.3,73.9) v1(109.3,74.5) ; v1(114.15,74.188) 114.379,73.959 114.8,73.959 ; C67.1@114.826,73 114.825,73.934 114.8,73.959 ; v1(116.2,74.2) 115.959,73.959 v1(115.635,73.959) 114.8,73.959
  other v1: 111.5,11.1 112.2,11.1 113.6,11.1 114.3,11.1
  other v3: 120.75,37.545
+24V: C2.1 C25.1 C104.1 C105.1 C108.1 C121.1 IC6.3 IC6.4 IC6.5 L11.1 L13.3 R41.2 T11.1 T11.2 T11.3 TP2.1 Z1.2 | length 2.7
  Bottom Layer w0.381: v3(45.8,10.4) 47.463,10.4 Z1.2@47.5,10.363
  Bottom Layer w0.762: C108.1@36.026,17.43 v3(37,17.43)
  other v3: 88.6,12.6 89.4,12.6 88.6,13.5 89.4,13.5 43.8,15.76 44.7,15.8 44.7,17 43.8,17.03 43.8,18.3 44.7,18.3
+24V_IN: C97.1 C106.1 D1.2 D22.2 F1.2 L13.2 | length 17.8
  Top Layer w1.016: F1.2@18.7,17.15 F1.2@19,17.45
  Bottom Layer w0.762: C106.1@14.625,13.279 D1.2@18,13.279
  Bottom Layer w0.889: D1.2@18,14.1 19.3,15.4 v3(19.8,15.4) v3(20.5,15.4) 20.5,7.2 19.01,7.2 D22.2@18.11,8.1
+VPSE: C1.1 C120.1 C122.1 D9.2 IC4.4 IC4.6 IC4.36 IC4.40 IC4.44 IC4.48 IC6.1 R41.1 RSH0.1 RSH1.1 RSH2.1 RSH3.1 RSH4.1 T10.3 T11.mb | length 86.8
  Top Layer w0.203: IC6.1@48.1,11.8 48.1,12.575 ; RSH0.1@51.55,31.4 51.55,32.33 51.72,32.5 53.063,32.5 53.444,32.119 53.444,29.506 61.2,21.75 IC4.4@63.1,21.75 ; RSH1.1@58.05,31.4 58.05,32.33 58.22,32.5 59.563,32.5 59.944,32.119 59.944,27.549 61.593,25.9 63,25.9 63.75,25.15 IC4.48@63.75,23.9 ; 60.125,21.025 60.4,20.75 IC4.6@63.1,20.75 ; RSH2.1@64.55,31.4 64.55,32.33 64.72,32.5 66.063,32.5 66.444,32.119 66.444,29.201 65.75,28.507 IC4.44@65.75,23.9 ; IC4.40@67.75,23.9 67.75,25.932 70.418,28.6 71.9,28.6 72.944,29.644 72.944,32.119 72.563,32.5 71.22,32.5 71.05,32.33 RSH3.1@71.05,31.4 ; IC4.36@69.9,23.25 71.468,23.25 71.8,23.582 71.8,25.782 75.018,29 79.093,29 79.444,29.351 79.444,32.119 79.063,32.5 77.72,32.5 77.55,32.33 RSH4.1@77.55,31.4
  Top Layer w0.508: 59.734,21.416 60.125,21.025
  Top Layer w1.016: 55.2,22.8 58.35,22.8 59.734,21.416
  other v1: 50.1,30.1 50.9,30.1 56.6,30.1 57.4,30.1 58.2,30.1 59,30.1 63.1,30.1 63.9,30.1 64.7,30.1 65.5,30.1 69.6,30.1 70.4,30.1 71.2,30.1 72,30.1 76.1,30.1 76.9,30.1 77.7,30.1 78.5,30.1 51.7,30.6 52.5,30.6 50.1,30.9 56.6,30.9 63.1,30.9 69.6,30.9 76.1,30.9 50.1,31.7 56.6,31.7 63.1,31.7 69.6,31.7 76.1,31.7
  other v3: 48,20.5 50,20.5 52,20.5 49,22 51,22 48,23.5 50,23.5 52,23.5 49,25 51,25 48,26.5 50,26.5 52,26.5 49,28 51,28
A0: IC12.1 IC12.2 IC12.3 IC12.7 R87.1 X12.1 X12.3 X12.4 X12.5 | length 38.3
  Top Layer w0.203: R87.1@108.326,49.8 108.39,49.865 IC12.7@110.76,49.865 IC12.2@115.44,49.865 ; IC12.1@115.44,48.595 IC12.2@115.44,49.865 ; IC12.3@115.44,51.135 IC12.2@115.44,49.865
  Top Layer w0.3: IC12.1@115.445,48.59 v1(116.9,48.59)
  Signal Layer 3 w0.203: v1(116.9,48.59) 117.76,49.45 132.97,49.45 X12.1@135.19,47.23
  Bottom Layer w0.254: X12.1@135.19,47.23 X12.3@137.73,47.23 ; X12.4@137.73,49.77 X12.3@137.73,47.23 ; X12.5@140.27,47.23 X12.3@137.73,47.23
ATEST/FXLOSEN: IC13.8 R84.2 | length 6
  Top Layer w0.152: R84.2@112.2,78.375 112.2,77.25 113.451,75.999 113.451,74.061 113.95,73.562 IC13.8@113.95,73.05
CLK25_REF: IC9.7 TP3.1 | length 10.3
  Top Layer w0.254: v1(51,69.6) 51.35,69.25 IC9.7@51.35,67.95 ; v1(53.6,74.4) TP3.1@54.9,74.4
  Bottom Layer w0.254: v1(51,69.6) 51,74.05 51.35,74.4 v1(53.6,74.4)
D_N: D17.1 D17.6 R64.1 R65.1 T1.4 | length 28.1
  Top Layer w0.254: T1.4@20.295,67.35 v3@20.295,68.98 ; v3(20.3,69) 21.325,70.026 R64.1@41.4,70.026 R65.1@43,70.026
  Bottom Layer w0.203: v3@20.305,69.021 21.405,69.021 21.805,68.621 D17.6@21.805,66.925
D_P: D17.2 D17.5 R68.1 R69.1 T1.1 | length 30.4
  Top Layer w0.254: v3(24.1,69) 39,69 39.5,68.5 39.5,62.975 40.4,62.075 R68.1@43,62.075 ; T1.1@24.105,67.32 v3@24.105,68.955
  Bottom Layer w0.203: D17.5@22.205,66.925 22.205,68.7 22.525,69.021 v3@24.105,69.021
Data_N: D31.1 D32.2 L6.1 L10.2 T1.5 | length 35.1
  Top Layer w0.381: v5@19.495,50.4 19.495,50.6 19.495,56.095 20.295,56.895 T1.5@20.295,58.82
  Top Layer w1.016: L6.1@20.1,50.6 19.495,50.6 v5(19.1,50.6) v5@19.1,49.55 ; L6.1@20.355,49.455 19.1,49.455 v5(19.1,49.5) v5@19.1,49.55 ; L6.1@20.8,50 19.55,50 v5@19.1,49.55
  Bottom Layer w1.016: 20.2,49.5 v5(19.1,50.6) v5(19.1,49.5) 19.8,49.5 23.5,49.5 D31.1@25.8,47.2 ; D32.2@25.8,43.6 D31.1@25.8,47.2 ; L10.2@29.4,43.6 L10.2@29.4,45.1 29.4,47.2 D31.1@25.8,47.2
Data_P: D34.1 D35.2 L6.2 L8.2 T1.8 | length 37.7
  Top Layer w0.381: L6.2@23.17,50.05 23.17,51.82 24.1,52.75 T1.8@24.1,58.82
  Top Layer w1.016: L6.2@23.17,50.05 26.309,50.05 27.7,48.659 v5(27.7,39.76) v5(27.7,38.66)
  Bottom Layer w1.016: D35.2@25.8,35.7 D34.1@25.8,39.2 ; D34.1@26.34,38.66 v5(27.7,38.66) L8.2@29.06,38.66 ; D34.1@26.34,38.86 D34.1@26,39.2 ; D34.1@26.36,39.76 v5(27.7,39.76) ; v5@27.7,39.8 L8.2@29.04,39.8 ; L8.2@29.4,39.2 D34.1@26,39.2 ; D34.1@25.8,39.2 D34.1@26,39.2 ; D34.1@25.8,39.2 D34.1@25.8,39.4 D34.1@26,39.2
E\T\H\_\R\S\T\: IC5.48 R73.1 R75.1 S2.2 S2.4 | length 45.7
  Top Layer w0.254: IC5.48@82.025,46.63 82.295,46.9 ; IC5.48@82.295,46.633 82.295,46.9 ; v1(82.3,50.2) 82.3,46.905 82.295,46.9 ; v1(82.5,71.061) 84.9,73.461 84.9,81.226 R73.1@86.1,82.426 R75.1@87.7,82.426 S2.4@89.376,82.426 ; S2.4@89.45,82.5 S2.4@89.8,82.5 S2.2@93.2,82.5 S2.2@93.55,82.5
  Bottom Layer w0.254: v1(82.3,50.2) 82.3,61.475 81.6,62.175 81.6,70.161 v1(82.5,71.061)
EECLK: IC1.19 IC3.2 | length 15.4
  Top Layer w0.203: IC1.19@123.65,29.2 123.65,28.296 123.754,28.193 123.754,23.197 124.589,22.361 126.796,22.361 127.646,21.511 127.646,18.546 127.365,18.265 IC3.2@126,18.265
EECS: IC1.16 IC3.1 R18.1 | length 17.2
  Top Layer w0.203: IC1.16@122.15,29.2 122.15,28.155 122.706,27.599 122.706,21.438 123.844,20.3 123.844,17.421 124.269,16.995 IC3.1@126,16.995 R18.1@128.421,16.995
EEDI: IC1.17 IC3.4 | length 11.2
  Top Layer w0.203: IC1.17@122.65,29.2 122.65,28.205 123.037,27.818 123.037,22.163 v3(123.5,21.7)
  Top Layer w0.254: IC3.4@126,20.805 v3(126,21.7)
  Bottom Layer w0.254: v3(123.5,21.7) v3(126,21.7)
EEDO: IC1.18 IC3.3 | length 11.7
  Top Layer w0.203: IC1.18@123.15,29.2 123.15,28.225 123.406,27.969 123.406,22.843 124.354,21.895 124.354,19.746 124.565,19.535 IC3.3@126,19.535
FXSDA/FXLOSA: IC13.9 R82.1 | length 6.6
  Top Layer w0.152: R82.1@110.3,78.375 112.943,75.731 112.943,74.061 113.45,73.554 IC13.9@113.45,73.05
FXSDB/FXLOSB: IC13.10 R88.1 | length 8
  Top Layer w0.152: R88.1@108.3,78.375 109.566,77.109 110.791,77.109 112.435,75.465 112.435,74.061 112.95,73.546 IC13.10@112.95,73.05
GND: C2.2 C3.2 C4.2 C5.2 C6.2 C9.2 C10.2 C11.2 C12.2 C13.2 C14.2 C15.1 C16.2 C17.1 C18.2 C19.1 C20.2 C21.2 C22.2 C23.2 C24.2 C25.2 C26.2 C27.2 C28.2 C29.2 C30.1 C31.1 C32.2 C37.2 C40.2 C41.2 C43.2 C44.2 C45.2 C46.2 C47.2 C48.2 C49.2 C50.2 C51.2 C52.2 C53.1 C54.1 C55.1 C56.1 C57.2 C58.2 C59.2 C60.2 C61.2 C62.2 C63.2 C64.2 C65.2 C66.1 C67.2 C68.2 C69.2 C70.2 C71.2 C72.2 C73.1 C74.2 C75.2 C76.2 C77.2 C78.2 C79.2 C80.2 C81.2 C82.1 C83.1 C84.1 C85.2 C86.2 C87.2 C88.2 C89.2 C90.2 C91.2 C92.2 C93.2 C94.2 C95.2 C96.2 C98.2 C99.2 C100.2 C101.2 C102.2 C103.2 C104.2 C105.2 C109.1 C110.1 C111.1 C112.2 C113.2 C114.2 C115.2 C116.2 C117.2 C118.2 C120.2 C121.2 C123.2 C124.2 C125.2 C126.2 C127.1 D5.1 D6.1 D7.1 D8.1 D10.1 D17.3 D18.1 D20.1 D21.1 D25.1 D26.3 IC1.49 IC2.10 IC2.13 IC3.5 IC4.21 IC4.24 IC4.49 IC5.7 IC9.41 IC10.3 IC11.2 IC12.4 IC13.4 IC13.59 IC13.89 L13.4 R2.2 R7.2 R9.2 R11.2 R12.2 R15.2 R17.2 R18.2 R19.1 R20.1 R21.1 R22.1 R23.1 R24.2 R25.2 R26.1 R33.1 R34.2 R37.1 R43.2 R82.2 R83.2 R84.1 R87.2 R88.2 R106.1 R107.1 R108.1 R109.1 R110.1 R111.1 R144.1 R145.1 R146.1 R147.1 R148.1 R149.1 R151.1 S2.1 S2.3 S3.2 S3.4 S4.2 S4.4 T4.2 T7.1 T7.2 T7.3 T8.2 TP11.1 VAR1.1 VAR2.2 X1.A1 X1.A12 X1.B1 X1.B12 X1.SH1 X1.SH2 X1.SH3 X1.SH4 X7.P11 X9.3 X11.3 X12.7 Y1.2 Y1.4 Y2.2 Y2.4 Y3.2 Y3.4 Y4.2 Y4.4 | length 169.5
  Top Layer w0.203: IC4.24@69.25,17.1 69.25,14.95 69.962,14.237 69.962,13 69.962,11.934 70.131,11.765 T7.3@71.375,11.765
  Top Layer w0.254: IC4.49@66.5,20.375 IC4.49@66.5,20.5 IC4.49@67.75,19.25 ; IC4.21@67.75,17.1 IC4.49@67.75,19.25 ; IC4.24@69.25,17.1 69.245,17.105 69.245,17.755 67.83,19.17 IC4.49@67.75,19.25 ; v1@77.75,45.8 IC5.7@77.75,47.925 77.75,49.189 ; IC13.59@113.95,60.95 113.95,61.66 v1(114.213,61.923) ; v2(125.087,66.059) 125.347,65.8 D26.3@126.925,65.8
  Top Layer w0.3: v1(68.2,11.025) R9.2@68.2,11.9 ; v1(87.526,78.126) C66.1@88.4,78.126 ; v1(90.9,49.9) R148.1@91.775,49.9 ; v1(90.9,51.7) R149.1@91.775,51.7 ; v1(90.9,53.5) R147.1@91.775,53.5 ; v1(90.9,55.3) R146.1@91.775,55.3 ; v1(90.9,57.1) R145.1@91.775,57.1 ; v1(90.9,58.9) R144.1@91.775,58.9 ; v1(90.9,63.6) R110.1@91.775,63.6 ; v1(90.9,65.4) R111.1@91.775,65.4 ; v1(90.9,67.2) R109.1@91.775,67.2 ; v1(90.9,69) R108.1@91.775,69 ; v1(90.9,70.8) R107.1@91.775,70.8 ; v1(90.9,72.6) R106.1@91.775,72.6 ; v1(91.4,77.3) IC11.2@92.4,77.3 ; C114.2@95.201,43.726 v1(95.201,44.6) ; C115.2@96.9,43.726 v1(96.901,44.6) ; v1(97.55,75.526) T4.2@97.55,76.4 ; IC10.3@97.6,80.65 v1(97.6,81.6) ; D25.1@100.6,82.45 v1(101.474,82.45) ; v1(100.8,48.7) R151.1@100.8,49.575 ; v1(105.8,49.8) R87.2@106.675,49.8 ; v1(106.7,47.4) C84.1@106.7,48.275 ; R88.2@108.3,80.026 v1(108.3,81) ; R82.2@110.3,80.026 v1(110.3,81) ; R84.1@112.2,80.026 v1(112.2,81) ; IC12.4@115.44,52.405 115.445,52.4 v1(116.9,52.4) ; C78.2@120.2,73.826 v1(120.2,74.8) ; C82.1@121.6,76.3 v1(122.474,76.3) ; C126.2@124.2,75.6 v1(124.2,76.474) ; C112.2@126,75.526 v1(126,76.4) ; C113.2@127.6,75.526 v1(127.6,76.4)
  Top Layer w0.381: v3(42.9,22.2) D20.1@44.05,22.2 ; v1(58.1,17.3) 58.975,17.3 C32.2@59,17.275 ; v1(58.126,12.326) 59,12.326 R37.1@58.974,12.3 ; v3(65.4,44.5) 66.1,44.5 S4.2@66.4,44.2 66.45,44.15 D21.1@66.45,38.1 ; C118.2@66.074,48 C118.2@66.375,47.7 ; X1.A1@144,29.3 X1.A1@144.42,29.3 ; X1.A12@144,34.9 X1.B1@145.67,34.9 X1.B1@145.67,34.1 ; X1.B12@145.67,30.1 X1.B12@145.67,29.3 X1.A1@144.42,29.3 ; C127.1@145.9,24.2 145.9,25.3 v3(144.9,26.3) 144.42,26.78 X1.A1@144.42,29.3
  Top Layer w0.45: C18.2@119.2,41 v3(119.2,41.953) ; v3(120.09,23.982) C16.2@120.09,24.935 ; C16.2@120.154,24.998 v3(121.106,24.998) 121.932,24.998 121.995,24.935 v3(121.995,23.982) ; C20.2@120.8,41.026 v3(120.8,41.978) ; v3(121.825,21.848) C17.1@121.825,22.8 ; C6.2@122.5,41.026 v3(122.5,41.978) ; C5.2@124.1,41.026 v3(124.1,41.978) ; v3(124.5,24.002) C21.2@124.5,24.955 ; v3(126,24.002) C3.2@126,24.955 ; C24.2@126.3,41.026 v3(126.3,41.978) ; C23.2@127.9,41.026 v3(127.9,41.978) ; R11.2@131.3,37.18 v2(132.174,37.18) ; C9.2@131.326,28.38 v2(132.2,28.38) ; C4.2@131.326,31.98 v2(132.2,31.98) ; C22.2@131.351,35.455 v2(132.225,35.455) ; R12.2@135.1,37.226 v2(135.1,38.1)
  Top Layer w0.508: v3(94.251,27.7) C99.2@95.175,27.7 ; v3(94.251,30.7) C100.2@95.175,30.7 ; v3(94.251,33.7) C101.2@95.175,33.7 ; v3(94.251,36.7) C102.2@95.175,36.7 ; C15.1@114.1,25.9 v3(114.1,26.825) ; v3(114.925,28.28) C13.2@115.849,28.28 ; v3(114.95,30.5) C12.2@115.875,30.5 ; v3(114.95,32.7) C11.2@115.875,32.7 ; v3(114.95,34.8) C10.2@115.875,34.8 ; v3(114.95,37.8) C29.2@115.875,37.8 ; v3(114.95,39.4) R7.2@115.875,39.4 ; v3(115.9,17) C40.2@116.875,17 ; v3(115.9,19.5) R17.2@116.875,19.5 ; R18.2@128.5,18.726 v3(128.5,19.65) ; v3(139.05,28) R2.2@139.975,28 v3(139.975,27.076)
  Top Layer w0.6: v1(48.4,59.4) C65.2@49.275,59.4 ; C73.1@114.3,77.026 v1(114.3,78) ; C74.2@116.4,77.026 v1(116.4,78) ; v1(123,65.726) R83.2@123,66.6
  Top Layer w0.635: C118.2@66.074,48 v1(65.5,48) 65.5,47.65 ; C118.2@66.375,47.7 C118.2@66.325,47.65 ; 65.5,47.65 C118.2@66.325,47.65 ; 65.5,47.65 v1(65.5,47.3) 65.975,47.3 C118.2@66.325,47.65
  Top Layer w0.7: C71.2@111.525,56.8 v1(112.3,56.8) C76.2@113.1,56.8
  Top Layer w0.762: v1(68.2,11.025) 68.2,10.4 68.25,10.35 v1@68.75,9.85 ; R9.2@68.2,11.874 68.2,8.95 R25.2@68.7,8.45 ; R25.2@68.7,8.45 68.7,9.8 v1@68.75,9.85 ; R25.2@68.7,8.45 69.165,8.915 69.165,9.435 v1@68.75,9.85
  Top Layer w1.016: L13.4@35.35,14.83 v3(37,14.83)
  Signal Layer 2 w0.381: X1.B12@145.67,29.3 X1.B12@145.67,30.1 ; X1.B1@145.67,34.1 X1.B1@145.67,34.9
  Bottom Layer w0.203: D17.3@22.6,67.875 22.6,68.532
  Bottom Layer w0.254: v1(100.9,61.9) 101.1,62.1 C70.2@102.074,62.1 ; v1(100.9,66.5) C75.2@101.974,66.5 ; v1(100.9,68.6) C69.2@102.074,68.6
  Bottom Layer w0.3: R33.1@89.1,27.126 v1(89.1,28) ; C72.2@117.1,56.8 v1(118.1,56.8)
  Bottom Layer w0.381: R26.1@54.275,43.7 54.3,43.675 v1(54.3,42.8) 58.2,42.8 v1(59.1,43.7) D18.1@59.95,43.7 ; v1(57.126,45.375) C117.2@58,45.375 ; T8.2@58,50.75 v1(58.875,50.75) ; v1(119,73.8) 121.475,73.8 C85.2@121.5,73.825
  Bottom Layer w0.45: C51.2@127.9,41.204 v3(127.9,41.978) ; C47.2@131.426,31.98 v2(132.2,31.98)
  Bottom Layer w0.508: v3(94.251,33.7) C98.2@96.775,33.7 ; v3@109.5,27 C103.2@110.501,27 ; v3(114.95,32.7) C49.2@115.875,32.7 ; v3(114.95,34.8) C48.2@115.875,34.8 ; v3(124.5,24.002) C50.2@124.5,24.777 ; v3(126,24.002) C46.2@126,24.777
  Bottom Layer w0.6: v1(107.7,72.1) C68.2@107.7,72.975 ; v1(113.174,72.126) C67.2@113.175,73
  Bottom Layer w0.635: R15.2@64.45,47.3 v1(65.5,47.3) 65.5,47.7 ; R15.2@64.45,47.7 65.5,47.7 ; R15.2@64.45,48 v1(65.5,48) 65.5,47.7
  Bottom Layer w0.762: C109.1@36.026,14.83 v3(37,14.83) ; D7.1@42.5,51.4 42.5,52.7 ; D7.1@42.5,51.4 42.9,51.8 v1(42.9,52.7) 42.5,52.7 ; D7.1@42.5,51.4 42.1,51.8 v1(42.1,52.7) 42.5,52.7 ; D8.1@42.5,54.9 42.1,55.3 v1(42.1,56.2) 42.5,56.2 ; D8.1@42.5,54.9 42.9,55.3 v1(42.9,56.2) 42.5,56.2 ; D8.1@42.5,54.9 42.5,56.2 ; D6.1@63.3,54.2 63.7,54.6 v1(64.6,54.6) 64.6,54.2 ; D6.1@63.3,54.2 63.7,53.8 v1(64.6,53.8) 64.6,54.2 ; D6.1@63.3,54.2 64.6,54.2
  other v1: 141.5,4.5 142.2,4.5 96.5,7.1 97.2,7.1 126,7.5 136,7.5 87.1,8.1 91.7,8.1 94.2,8.1 87.1,8.8 68.2,9.6 68.9,9.6 68.2,10.3 100.5,11.2 102,11.2 103.5,11.2 106.6,11.8 70.3,12 106.6,12.5 120.6,12.5 131,12.5 141,12.5 100.5,12.7 102,12.7 103.5,12.7 70.3,13 70.3,14 100.5,14.2 103.5,14.2 53.9,14.8 111.9,14.8 114,14.8 70.3,15 71.4,15.2 53.9,15.6 100.5,15.7 102,15.7 103.5,15.7 95.3,16.6 102,17.2 103.5,17.2 136,17.5 111,22.5 131,22.5 141,22.5 91,32.5 40.8,38.7 41.7,38.7 42.6,38.7 40.8,39.7 40.8,40.6 40.8,41.4 41.7,41.4 42.6,41.4 77.8,41.7 91,42.5 101,42.5 111,42.5 131,42.5 141,42.5 79.6,42.7 77.8,43.7 79.6,44.9 147.6,45.7 77.8,45.8 147.6,46.4 48.9,48 49.6,48 147.6,48.5 147.6,49.2 80.2,51.32 147.6,51.9 131,52.5 141,52.5 147.6,52.6 75.15,53.1 76.675,54.174 44.821,59.4 44.821,60.797 44,61.8 30.7,65.5 30.7,66.2 47.456,70.905 48.646,71.975 6.1,72.3 6.8,72.3 8.8,72.3 9.5,72.3 11.4,72.3 12.1,72.3 42.7,73 43.6,73.8 45.2,75.3 11,75.5 21,75.5 31,75.5 41,75.5 51,75.5 61,75.5 71,75.5 81,75.5 122.95,77.92 131,78.5 131.7,78.5 134,78.5 134.7,78.5 137.4,78.6 138.1,78.6 128.4,79.5 129.1,79.5 117.9,79.7 16,80.5 26,80.5 36,80.5 46,80.5 56,80.5 66,80.5 76,80.5 119.425,80.775 18.4,82.1 19.1,82.1
  other v2: 64.264,18.284 65.157,18.284 66.05,18.284 66.944,18.284 67.837,18.284 68.73,18.284 64.264,19.177 65.157,19.177 66.05,19.177 66.944,19.177 67.837,19.177 68.73,19.177 64.264,20.07 65.157,20.07 66.05,20.07 66.944,20.07 67.837,20.07 68.73,20.07 64.264,20.963 65.157,20.963 66.05,20.963 66.944,20.963 67.837,20.963 68.73,20.963 64.264,21.857 65.157,21.857 66.05,21.857 66.944,21.857 67.837,21.857 68.73,21.857 64.264,22.75 65.157,22.75 66.05,22.75 66.944,22.75 67.837,22.75 68.73,22.75 121.164,30.384 122.057,30.384 122.95,30.384 123.844,30.384 124.737,30.384 125.63,30.384 121.164,31.277 122.057,31.277 122.95,31.277 123.844,31.277 124.737,31.277 125.63,31.277 121.164,32.17 122.057,32.17 122.95,32.17 123.844,32.17 124.737,32.17 125.63,32.17 121.164,33.064 122.057,33.064 122.95,33.064 123.844,33.064 124.737,33.064 125.63,33.064 121.164,33.957 122.057,33.957 122.95,33.957 123.844,33.957 124.737,33.957 125.63,33.957 121.164,34.85 122.057,34.85 122.95,34.85 123.844,34.85 124.737,34.85 125.63,34.85 50.757,63.677 51.65,63.677 52.544,63.677 53.437,63.677 50.757,64.57 51.65,64.57 52.544,64.57 53.437,64.57 109.964,64.784 110.857,64.784 111.75,64.784 112.644,64.784 113.537,64.784 114.43,64.784 50.757,65.464 51.65,65.464 52.544,65.464 53.437,65.464 109.964,65.677 110.857,65.677 111.75,65.677 112.644,65.677 113.537,65.677 114.43,65.677 50.757,66.357 51.65,66.357 52.544,66.357 53.437,66.357 109.964,66.57 110.857,66.57 111.75,66.57 112.644,66.57 113.537,66.57 114.43,66.57 109.964,67.464 110.857,67.464 111.75,67.464 112.644,67.464 113.537,67.464 114.43,67.464 109.964,68.357 110.857,68.357 111.75,68.357 112.644,68.357 113.537,68.357 114.43,68.357 109.964,69.25 110.857,69.25 111.75,69.25 112.644,69.25 113.537,69.25 114.43,69.25
  other v3: 38,3.2 40,3.2 42,3.2 44,3.2 46,3.2 48,3.2 50,3.2 52,3.2 35,4.5 37,4.5 39,4.5 45,4.5 47,4.5 49,4.5 51,4.5 36,6 38,6 40,6 35,7.5 37,7.5 39,7.5 36,9 38,9 35,10.5 37,10.5 39,10.5 36,12 38,12 35,13.5 37,13.5 39,13.5 109.5,26.6 109.5,27.3 122.9,43.747 124.3,43.747 126.575,43.747 127.803,43.747 128.942,43.747 122.9,46.85 122.9,47.85 124.4,47.85 125.9,47.85 127.4,47.85 128.9,47.85
GPIO0: D27.1 IC13.66 | length 8.4
  Top Layer w0.178: IC13.66@117.45,60.95 117.958,60.95 118.2,60.708 118.2,59.631 118.47,59.361 123.089,59.361 D27.1@124.1,58.35
GPIO1: IC13.64 R89.2 | length 4.5
  Top Layer w0.147: IC13.64@116.45,60.95 116.45,60.355 116.3,60.205 116.3,57.6 R89.2@117.1,56.8
GPIO2: D28.1 IC13.63 | length 8.8
  Top Layer w0.147: IC13.63@115.95,60.95 115.95,56.512 116.463,56 118.85,56 D28.1@119.7,56.85
GPIO3: IC13.47 X7.P9 | length 42.5
  Top Layer w0.152: 107.155,59.6 107.95,60.395 ; 107.155,59.6 v1(106.6,59.6) 107.155,59.6 ; 107.155,59.6 107.95,60.395 ; 107.95,60.395 IC13.47@107.95,60.95 107.95,60.395
  Signal Layer 3 w0.203: v1(106.6,59.6) 108.7,57.5 129.1,57.5 129.5,57.9 129.5,69.385 X7.P9@131.38,71.265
